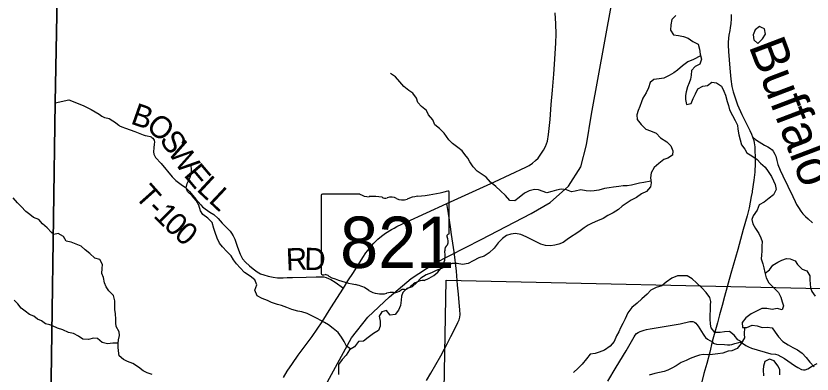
# Model space of a CAD drawing. Extents: x 0 to 34, y 0 to 22.
# Drawn here: x 26.994 to 29.042, y 17.376 to 18.296 of the extents above; entities that cross this region are included whole.
import ezdxf

# ---------------------------------------------------------------- set-up
doc = ezdxf.new("R2010")
doc.units = 0
for name, color, linetype in [('GM_X_Corporation', 7, 'Continuous'), ('GM_X_County_Road', 7, 'Continuous'), ('GM_X_Minor_Lake', 7, 'Continuous'), ('GM_X_Minor_River', 7, 'Continuous'), ('GM_X_Minor_River_Text', 7, 'Continuous'), ('GM_X_Rail_Line', 7, 'Continuous'), ('GM_X_State_Location', 7, 'Continuous'), ('GM_X_State_Route', 7, 'Continuous'), ('GM_X_State_Shield', 7, 'Continuous'), ('GM_X_Township_Road', 7, 'Continuous'), ('GM_X_Township_Road_Text', 7, 'Continuous')]:
    doc.layers.add(name, color=color, linetype=linetype)

msp = doc.modelspace()

# ---------------------------------------------------------------- linework, layer by layer
at = {"layer": 'GM_X_Corporation'}
for points in [[(26.6535, 14.621), (27.01, 14.6164), (27.046, 14.6155), (27.043, 14.755), (27.052, 15.403), (27.0676, 16.5549), (27.0694, 16.6556), (27.0775, 16.888), (27.0944, 18.0731), (27.1039, 18.5696), (27.1064, 18.6537), (27.3971, 18.6436), (28.3421, 18.6121), (28.7772, 18.6028), (29.0074, 18.5935), (29.6561, 18.5791), (29.6772, 18.5786), (30.101, 18.5701), (30.3167, 18.565), (30.3167, 20.9), (23.5167, 20.9)], [(26.3378, 16.673), (27.0694, 16.6556), (27.0775, 16.888), (27.0944, 18.0731), (27.1039, 18.5696), (27.1064, 18.6537), (27.3971, 18.6436), (28.3421, 18.6121), (28.7772, 18.6028), (29.0074, 18.5935), (29.6561, 18.5791), (29.6772, 18.5786), (30.101, 18.5701), (30.3167, 18.565), (30.3167, 20.9), (25.1014, 20.9)], [(23.5167, 14.1), (30.3167, 14.1), (30.3167, 18.565), (30.101, 18.5701), (29.6772, 18.5786), (29.6561, 18.5791), (29.0074, 18.5935), (28.7772, 18.6028), (28.3421, 18.6121), (27.3971, 18.6436), (27.1064, 18.6537), (27.1039, 18.5696), (27.0944, 18.0731), (27.0775, 16.888), (27.0694, 16.6556), (27.0676, 16.5549), (27.052, 15.403), (27.043, 14.755), (27.046, 14.6155), (27.01, 14.6164), (26.6535, 14.621)], [(27.1039, 18.5696), (27.0944, 18.0731), (27.0775, 16.888), (27.0694, 16.6556), (27.0676, 16.5549), (27.052, 15.403)]]:
    msp.add_lwpolyline(points, dxfattribs=at)
msp.add_lwpolyline([(28.101, 17.617), (29.1032, 17.5952), (29.0727, 16.6129), (28.0831, 16.631)], close=True, dxfattribs=at)
at = {"layer": 'GM_X_County_Road'}
for points in [[(28.8892, 17.985), (28.8967, 17.9784), (28.9067, 17.9721), (28.9203, 17.9642), (28.9286, 17.9593), (28.9357, 17.9549), (28.9395, 17.9518), (28.942, 17.9488), (28.9469, 17.9409), (28.9489, 17.9356), (28.9521, 17.9245), (28.9546, 17.914), (28.9602, 17.9), (28.9676, 17.8852), (28.9803, 17.8583), (28.9927, 17.8318), (28.9987, 17.8193), (29.0027, 17.8111), (29.0076, 17.8036), (29.0137, 17.7947), (29.0191, 17.7877), (29.0254, 17.7809), (29.032, 17.7744), (29.0439, 17.764)], [(28.05, 17.359), (28.0611, 17.3783), (28.0874, 17.423), (28.0968, 17.4403), (28.1038, 17.4534), (28.1133, 17.4724), (28.1213, 17.4887), (28.1312, 17.5081), (28.1345, 17.5154), (28.1361, 17.5224), (28.137, 17.5285), (28.1365, 17.5412), (28.1344, 17.5599), (28.1323, 17.5808), (28.1301, 17.6041), (28.1277, 17.6398), (28.1217, 17.69), (28.1147, 17.7345), (28.1118, 17.7543), (28.107, 17.7883), (28.1029, 17.8137)]]:
    msp.add_lwpolyline(points, dxfattribs=at)
at = {"layer": 'GM_X_Minor_Lake'}
for points in [[(28.9122, 18.2663), (28.9071, 18.2689), (28.8957, 18.2602), (28.8908, 18.2473), (28.8927, 18.2344), (28.9032, 18.2249)], [(28.9032, 18.2249), (28.9146, 18.237), (28.9222, 18.2491), (28.9199, 18.2624), (28.9122, 18.2663)]]:
    msp.add_lwpolyline(points, dxfattribs=at)
at = {"layer": 'GM_X_Minor_River'}
for points in [[(28.692, 18.2972), (28.6817, 18.287), (28.6787, 18.2733), (28.6783, 18.2597), (28.6858, 18.2476), (28.6987, 18.2453), (28.7112, 18.243), (28.7233, 18.2384), (28.7357, 18.2304), (28.7497, 18.2236), (28.7527, 18.2107), (28.7542, 18.1978), (28.7583, 18.1849), (28.7534, 18.1724), (28.7416, 18.1656), (28.7322, 18.1554), (28.7314, 18.1433), (28.7295, 18.1334), (28.7261, 18.1236), (28.7223, 18.1141), (28.7188, 18.1008), (28.7169, 18.0913), (28.7169, 18.0815), (28.7195, 18.0686), (28.7316, 18.0709), (28.7366, 18.0837), (28.7426, 18.0959), (28.7487, 18.1084), (28.7616, 18.1152), (28.7733, 18.117), (28.7843, 18.1254), (28.7968, 18.1238), (28.8092, 18.1155), (28.8153, 18.103), (28.8194, 18.0923), (28.8239, 18.0757), (28.8273, 18.0654), (28.8299, 18.0544), (28.8378, 18.0404), (28.8446, 18.0275), (28.8503, 18.015), (28.8514, 18.0047), (28.8536, 17.9903), (28.8574, 17.9774), (28.8608, 17.9649), (28.8694, 17.9536), (28.8743, 17.9441), (28.8875, 17.9361), (28.9015, 17.9274), (28.9094, 17.9179), (28.9219, 17.9072), (28.9298, 17.8959), (28.9377, 17.8837), (28.9434, 17.8723), (28.9475, 17.8625), (28.9498, 17.8496), (28.9429, 17.8367), (28.932, 17.828), (28.9191, 17.8178), (28.9062, 17.8102), (28.9013, 17.797), (28.8907, 17.7826), (28.8876, 17.7727), (28.8902, 17.7617), (28.897, 17.75), (28.9057, 17.7367), (28.911, 17.7261), (28.914, 17.7162), (28.9132, 17.7048), (28.9132, 17.692), (28.912, 17.6817), (28.9116, 17.6719)], [(28.7555, 18.1936), (28.7371, 18.1842), (28.7228, 18.1778), (28.7091, 18.1675), (28.6966, 18.1566), (28.6868, 18.1501), (28.6747, 18.143), (28.6614, 18.1361), (28.6489, 18.1339), (28.6357, 18.1324), (28.6259, 18.1248), (28.6217, 18.1112), (28.6152, 18.0987), (28.6072, 18.085), (28.6038, 18.0756), (28.5989, 18.0635), (28.5951, 18.0528), (28.5917, 18.0419), (28.5928, 18.0294), (28.6026, 18.0168), (28.615, 18.0054), (28.6267, 18.0009), (28.6411, 17.9944), (28.6528, 17.983), (28.6687, 17.9724), (28.6792, 17.9618), (28.6845, 17.9493), (28.683, 17.9383), (28.6709, 17.9307), (28.6606, 17.9269), (28.6485, 17.9167), (28.6364, 17.9069), (28.6281, 17.8928), (28.6269, 17.8796), (28.628, 17.8671), (28.6269, 17.8568), (28.6162, 17.8447), (28.6038, 17.8387), (28.5905, 17.8296), (28.5769, 17.8224), (28.567, 17.8156), (28.5542, 17.8069), (28.5443, 17.7982), (28.5303, 17.7903), (28.5167, 17.7831), (28.5049, 17.7759), (28.4902, 17.7691), (28.4762, 17.7634), (28.466, 17.7581), (28.4561, 17.7517), (28.4421, 17.7411), (28.416, 17.7237), (28.402, 17.7142), (28.391, 17.7097), (28.3804, 17.7071), (28.3698, 17.7056), (28.3569, 17.706), (28.3449, 17.7094), (28.3339, 17.7147), (28.3203, 17.7219), (28.3071, 17.7284), (28.2927, 17.7341), (28.2791, 17.7371), (28.2674, 17.7356), (28.256, 17.7319), (28.2458, 17.7239), (28.2344, 17.7129), (28.2242, 17.6997), (28.2117, 17.6876), (28.1985, 17.6789), (28.1852, 17.6747), (28.1705, 17.6664), (28.1576, 17.66), (28.1428, 17.6573), (28.1296, 17.6596), (28.1156, 17.6596), (28.1027, 17.6536), (28.0891, 17.6471), (28.0751, 17.6419), (28.063, 17.6362), (28.0498, 17.6305), (28.0361, 17.6222), (28.0251, 17.6108), (28.013, 17.5999), (27.9998, 17.5957), (27.9895, 17.5855), (27.9857, 17.576), (27.985, 17.5658), (27.9838, 17.5521), (27.9785, 17.54), (27.9694, 17.529), (27.9569, 17.5272), (27.9475, 17.5389), (27.935, 17.5359), (27.9289, 17.5245), (27.9308, 17.5116), (27.9315, 17.4988), (27.927, 17.4878), (27.9137, 17.4798), (27.9005, 17.4696), (27.8883, 17.4605)], [(28.6276, 17.8718), (28.6099, 17.8679), (28.5981, 17.866), (28.5879, 17.8633), (28.5777, 17.8611), (28.5664, 17.8596), (28.5561, 17.8592), (28.5456, 17.8581), (28.5319, 17.8558), (28.5202, 17.8539), (28.5081, 17.8524), (28.4934, 17.8487), (28.482, 17.8468), (28.4718, 17.8461), (28.4612, 17.8468), (28.4472, 17.8491), (28.4332, 17.8457), (28.423, 17.8442), (28.4102, 17.8488), (28.3969, 17.8511), (28.3848, 17.8484), (28.3727, 17.8447), (28.3599, 17.8416), (28.3383, 17.8489), (28.3281, 17.8496), (28.3145, 17.8463), (28.3024, 17.8402), (28.2887, 17.8292), (28.2774, 17.8209), (28.2649, 17.8221), (28.254, 17.8346), (28.2407, 17.8467), (28.2283, 17.8574), (28.2151, 17.8691), (28.2038, 17.8813), (28.1936, 17.8885), (28.1807, 17.8968), (28.1705, 17.9086), (28.1619, 17.9207), (28.1566, 17.9302), (28.1487, 17.9397), (28.1419, 17.9492), (28.1313, 17.9583), (28.1173, 17.9682), (28.1075, 17.9777), (28.0958, 17.9951), (28.0838, 18.0065), (28.0717, 18.0164), (28.0668, 18.0293), (28.0558, 18.0422), (28.0506, 18.0528), (28.0373, 18.063), (28.0283, 18.0733), (28.0242, 18.0843), (28.0151, 18.0972), (28.0049, 18.1044), (27.9917, 18.1143), (27.9815, 18.1268), (27.9702, 18.1393), (27.9577, 18.148)], [(27.8555, 17.4401), (27.8448, 17.4477), (27.8384, 17.4598), (27.8316, 17.4708), (27.8234, 17.4826), (27.8101, 17.4925), (27.7981, 17.5019), (27.7882, 17.508), (27.7784, 17.5133), (27.7686, 17.519), (27.7539, 17.5263), (27.7429, 17.5312), (27.7297, 17.5358), (27.7191, 17.5373), (27.7036, 17.5419), (27.6907, 17.5468), (27.6775, 17.5518), (27.6673, 17.5548), (27.6511, 17.5601), (27.6409, 17.5647), (27.6276, 17.5696), (27.6148, 17.5772), (27.6084, 17.5913), (27.6141, 17.6053), (27.6085, 17.6182), (27.5964, 17.6273), (27.5816, 17.6368), (27.5707, 17.6489), (27.5616, 17.6592), (27.5533, 17.6694), (27.5477, 17.6797), (27.5364, 17.691), (27.5254, 17.7028), (27.5179, 17.7123), (27.5119, 17.7248), (27.5062, 17.7392), (27.5028, 17.7502), (27.4987, 17.765), (27.4874, 17.776), (27.4745, 17.7859), (27.4685, 17.7954), (27.4647, 17.8098), (27.458, 17.8219), (27.4474, 17.8337), (27.4357, 17.8451), (27.4319, 17.8545), (27.4346, 17.8655), (27.4411, 17.8788), (27.4449, 17.8894), (27.4453, 17.9), (27.4449, 17.9133)], [(27.085, 17.7399), (27.0738, 17.7519), (27.0624, 17.7616), (27.0528, 17.7725), (27.0392, 17.7784), (27.0293, 17.7855), (27.0194, 17.7934), (27.0072, 17.8061), (26.998, 17.8159), (26.987, 17.8283)], [(27.344, 17.3748), (27.3312, 17.379), (27.3214, 17.3843), (27.3093, 17.3938), (27.2949, 17.4033), (27.2813, 17.4082), (27.2708, 17.4132), (27.2591, 17.4226), (27.2579, 17.4352), (27.2568, 17.4446), (27.2569, 17.4545), (27.2576, 17.464), (27.2599, 17.4746), (27.2592, 17.4844), (27.252, 17.4981), (27.2505, 17.5076), (27.2509, 17.517), (27.2498, 17.5303), (27.2479, 17.5417), (27.248, 17.5644), (27.2446, 17.5773), (27.2325, 17.5898), (27.2261, 17.6001), (27.222, 17.6099), (27.2194, 17.6236), (27.2145, 17.6338), (27.2156, 17.6471), (27.2168, 17.6573), (27.2096, 17.6702), (27.1971, 17.674), (27.1836, 17.6854), (27.1722, 17.6953), (27.162, 17.7044), (27.1488, 17.7094), (27.1356, 17.7147), (27.1227, 17.7174), (27.1159, 17.7295), (27.1027, 17.7367), (27.091, 17.7341), (27.085, 17.7399)], [(28.9116, 17.6719), (28.9154, 17.659), (28.9184, 17.6491), (28.921, 17.6366), (28.9244, 17.623), (28.9308, 17.6104), (28.9561, 17.585), (28.9617, 17.5733), (28.9659, 17.5615), (28.9692, 17.5513), (28.9658, 17.5406), (28.953, 17.5445), (28.9401, 17.5418), (28.9261, 17.5441), (28.9136, 17.5441), (28.8996, 17.5373), (28.886, 17.5309), (28.8724, 17.5207), (28.8625, 17.5082), (28.8636, 17.4953), (28.875, 17.4957), (28.8879, 17.5013), (28.9011, 17.4998), (28.9139, 17.4952), (28.9272, 17.4967), (28.94, 17.4944), (28.9476, 17.4838), (28.9559, 17.4717), (28.9672, 17.4599), (28.9808, 17.4508), (28.9929, 17.4443), (29.0046, 17.4383), (29.017, 17.4299), (29.0276, 17.4181), (29.037, 17.406), (29.048, 17.3946)], [(28.9214, 17.6348), (28.9331, 17.6438), (28.9418, 17.6555), (28.954, 17.6635), (28.9646, 17.6688), (28.9763, 17.6725), (28.9865, 17.6718), (28.9993, 17.6668), (29.005, 17.657), (29.0167, 17.6452), (29.0292, 17.641), (29.0363, 17.6285), (29.0371, 17.6175), (29.0374, 17.6073), (29.0385, 17.5978), (29.0419, 17.5883), (29.0506, 17.5762)], [(28.8622, 17.4579), (28.8515, 17.4635), (28.842, 17.476), (28.8303, 17.4851), (28.8175, 17.4844), (28.8058, 17.4825), (28.7925, 17.4825), (28.7831, 17.4943), (28.7808, 17.5038), (28.7805, 17.5174), (28.7805, 17.5276), (28.7809, 17.5401), (28.7813, 17.553), (28.7817, 17.5625), (28.7798, 17.5727), (28.77, 17.5853), (28.7591, 17.5978), (28.7455, 17.6103), (28.7338, 17.6202), (28.7213, 17.6278), (28.7077, 17.6282), (28.696, 17.6286), (28.6812, 17.6225), (28.6672, 17.6119), (28.6555, 17.6025), (28.6415, 17.5983), (28.6279, 17.5915), (28.618, 17.5809), (28.6047, 17.5688), (28.5922, 17.5582), (28.5786, 17.5469), (28.568, 17.5332), (28.5612, 17.5177), (28.5555, 17.5056), (28.5494, 17.4942), (28.5452, 17.484), (28.5391, 17.4737), (28.5331, 17.4594), (28.5225, 17.4476), (28.5084, 17.437), (28.4944, 17.4321), (28.4842, 17.4287), (28.4717, 17.4268), (28.4619, 17.4147), (28.4505, 17.4015), (28.4407, 17.3909), (28.4289, 17.3795)], [(27.0814, 17.5025), (27.0703, 17.5052), (27.06, 17.5127), (27.049, 17.5171), (27.0395, 17.5246), (27.0285, 17.529), (27.0175, 17.5373), (27.0072, 17.5451), (26.9984, 17.556), (26.9889, 17.5654)], [(27.2569, 17.4549), (27.2432, 17.4556), (27.2292, 17.4534), (27.2153, 17.4568), (27.2036, 17.4671), (27.1937, 17.4678), (27.1805, 17.4648), (27.1661, 17.4656), (27.1544, 17.4736), (27.1416, 17.4797), (27.1287, 17.4827), (27.1147, 17.4899), (27.1004, 17.4941), (27.0879, 17.4998), (27.0814, 17.5025)], [(28.8688, 17.4955), (28.8674, 17.4782), (28.8685, 17.4688), (28.8602, 17.4544), (28.8499, 17.4415), (28.8363, 17.4355), (28.8265, 17.4347), (28.8128, 17.4294), (28.8, 17.4279), (28.7864, 17.4257), (28.7724, 17.4253), (28.7625, 17.4257), (28.7527, 17.4242), (28.7421, 17.4212), (28.7292, 17.4159), (28.7186, 17.411), (28.7058, 17.4057), (28.6925, 17.3974), (28.6815, 17.3909), (28.6713, 17.386), (28.6615, 17.3826), (28.6377, 17.3773), (28.6233, 17.3728)], [(27.8883, 17.4605), (27.8755, 17.4594), (27.8653, 17.4461), (27.8524, 17.4382), (27.844, 17.4246), (27.8334, 17.4132), (27.8236, 17.4007), (27.8235, 17.3874), (27.8239, 17.3746)], [(28.9591, 17.3739), (28.9591, 17.3875), (28.9546, 17.397), (28.9452, 17.4099), (28.9327, 17.4137), (28.921, 17.408), (28.9171, 17.3959), (28.9167, 17.3864), (28.9175, 17.3717)]]:
    msp.add_lwpolyline(points, dxfattribs=at)
at = {"layer": 'GM_X_Rail_Line'}
msp.add_lwpolyline([(27.3982, 16.1548), (27.3854, 16.3634), (27.3867, 16.4413), (27.3961, 16.5113), (27.412, 16.582), (27.4321, 16.6447), (27.4659, 16.7237), (27.5061, 16.8023), (27.629, 17.0326), (27.7235, 17.2242), (27.8569, 17.4686), (27.899, 17.522), (27.9555, 17.5744), (28.0109, 17.6216), (28.0703, 17.6598), (28.1907, 17.7214), (28.3198, 17.7886), (28.3682, 17.817), (28.4153, 17.8583), (28.4471, 17.9079), (28.4621, 17.965), (28.4748, 18.0437), (28.5781, 18.607)], dxfattribs=at)
at = {"layer": 'GM_X_State_Route'}
for points in [[(27.6827, 17.3674), (27.6916, 17.3831), (27.7051, 17.4033), (27.7205, 17.4248), (27.7559, 17.4725), (27.782, 17.5104), (27.804, 17.5457), (27.8366, 17.5967), (27.8483, 17.6153), (27.8621, 17.6368), (27.8867, 17.6756), (27.8946, 17.6872), (27.8983, 17.6925), (27.9024, 17.6979), (27.9088, 17.7056), (27.915, 17.7124), (27.9208, 17.7182), (27.9255, 17.7226), (27.9305, 17.7269), (27.9376, 17.7325), (27.9446, 17.7377), (27.9603, 17.7472), (27.9674, 17.751), (27.9741, 17.7546), (27.9978, 17.7659), (28.1029, 17.8137), (28.2256, 17.8698), (28.3063, 17.9071), (28.3145, 17.9116), (28.323, 17.9179), (28.331, 17.9244), (28.3375, 17.9309), (28.343, 17.9382), (28.3515, 17.9511), (28.3565, 17.9605), (28.3616, 17.9743), (28.3643, 17.991), (28.3682, 18.0299), (28.3711, 18.0683), (28.3742, 18.1055), (28.3776, 18.1467), (28.3804, 18.1847), (28.3832, 18.227), (28.3836, 18.2491), (28.3829, 18.2756), (28.3815, 18.3037)], [(28.8341, 18.3), (28.8341, 18.2888), (28.8338, 18.2764), (28.8321, 18.2649), (28.8305, 18.2584), (28.8281, 18.2465), (28.8272, 18.2391), (28.8262, 18.2273), (28.8264, 18.2206), (28.8275, 18.2046), (28.8307, 18.1614), (28.8333, 18.1335), (28.8363, 18.1146), (28.8393, 18.1013), (28.8425, 18.0907), (28.8505, 18.0677), (28.8618, 18.0431), (28.8713, 18.0238), (28.8822, 18.0015), (28.8864, 17.9918), (28.8892, 17.985), (28.8924, 17.976), (28.8937, 17.9702), (28.8949, 17.96), (28.8956, 17.947), (28.896, 17.9367), (28.8959, 17.9174), (28.8951, 17.8944), (28.893, 17.8738), (28.8885, 17.8455), (28.8881, 17.8434)], [(28.8881, 17.8434), (28.8858, 17.8322), (28.8803, 17.8032), (28.8752, 17.7823), (28.8655, 17.7469), (28.8513, 17.6958), (28.8336, 17.6342), (28.8171, 17.5747), (28.811, 17.552), (28.8042, 17.5281), (28.799, 17.5074), (28.7858, 17.4592), (28.779, 17.432), (28.7714, 17.4032), (28.7643, 17.3775), (28.756, 17.3452)]]:
    msp.add_lwpolyline(points, dxfattribs=at)
at = {"layer": 'GM_X_State_Shield'}
for p, q in [((27.7794, 17.8345), (27.7794, 17.6343)), ((27.8791, 17.8379), (27.7826, 17.8379)), ((28.109, 17.7382), (28.109, 17.8429)), ((28.1089, 17.7382), (28.109, 17.7382))]:
    msp.add_line(p, q, dxfattribs=at)
for centre, major_axis, start_param, end_param in [((27.9916, 18.1107), (0.3495, 0), 4.814394, 5.042369), ((28.1053, 17.8433), (0.00367, 0), 6.141152, 7.989035), ((27.7832, 17.8349), (0.00382, 0), 1.712693, 3.28349), ((27.9021, 17.8611), (0.037, 0), 4.042523, 4.731795), ((27.9144, 17.7256), (0.133, 0), 1.404758, 1.657858), ((27.9446, 17.8359), (0.0107, 0), 3.836095, 5.185415), ((27.9603, 17.8128), (0.0222, 0), 0.950623, 2.079405), ((27.989, 17.8445), (0.0267, 0), 4.081561, 5.145723), ((28.0361, 17.7768), (0.0703, 0), 1.699011, 2.107814), ((28.1081, 17.7305), (0.00568, 0), 1.883978, 3.671073), ((28.072, 17.7173), (0.0341, 0), 5.934695, 6.695948), ((28.1051, 17.7378), (0.00393, 0), 5.05454, 6.418171), ((28.1221, 17.6944), (0.0248, 0), 2.387724, 3.262537), ((28.0111, 17.6811), (0.0874, 0), 5.101752, 6.440018), ((27.7832, 17.6339), (0.00385, 0), 3.00124, 4.508301), ((27.7838, 17.6544), (0.0294, 0), 4.665946, 4.897461), ((27.7898, 17.6228), (0.0106, 0), 0.519207, 1.627899), ((27.9236, 17.8026), (0.2524, 0), 4.195997, 4.488961), ((27.8484, 17.5444), (0.079, 0), 0.823519, 1.323587), ((27.9873, 17.615), (0.0282, 0), 4.937069, 5.64225), ((28.048, 17.5782), (0.0479, 0), 1.647645, 2.488434), ((27.9338, 17.6218), (0.0501, 0), 4.026481, 4.996735), ((27.9627, 17.5526), (0.0412, 0), 1.495662, 1.94098), ((27.9664, 17.6068), (0.0267, 0), 4.691044, 5.507374), ((27.9905, 17.5874), (0.00752, 0), 1.147584, 2.315152)]:
    msp.add_ellipse(centre, major_axis=major_axis, ratio=0.8, start_param=start_param, end_param=end_param, dxfattribs=at)
at = {"layer": 'GM_X_Township_Road'}
for points in [[(27.0946, 18.0726), (27.1303, 18.0802), (27.1672, 18.0655), (27.187, 18.0558), (27.2082, 18.0436), (27.2117, 18.0409), (27.2148, 18.0383), (27.2181, 18.0365), (27.2219, 18.0351), (27.2258, 18.0341), (27.2299, 18.0335), (27.2334, 18.0325), (27.2436, 18.0266), (27.2497, 18.0222), (27.2552, 18.0176), (27.2585, 18.0149)], [(27.2585, 18.0149), (27.2601, 18.0136), (27.2662, 18.0106), (27.2755, 18.0073), (27.2997, 17.999), (27.3213, 17.9905), (27.3267, 17.9891), (27.3319, 17.9878), (27.3389, 17.9859), (27.3415, 17.9851), (27.3438, 17.9838), (27.3464, 17.982), (27.3481, 17.9796), (27.3493, 17.9764), (27.3501, 17.9712), (27.3494, 17.9663), (27.3484, 17.9574), (27.3477, 17.9464), (27.3486, 17.9405), (27.3503, 17.937), (27.3532, 17.9322), (27.3672, 17.9165), (27.3957, 17.8826), (27.4057, 17.873), (27.4155, 17.8653), (27.4225, 17.8606), (27.4292, 17.8564), (27.4348, 17.8511), (27.4403, 17.8448), (27.4565, 17.8249), (27.4693, 17.8103), (27.4735, 17.8055), (27.4806, 17.7999), (27.4864, 17.7957), (27.4929, 17.7916), (27.5028, 17.7855), (27.5139, 17.7752), (27.5192, 17.7694), (27.5247, 17.7632), (27.5325, 17.7559), (27.5401, 17.748), (27.5447, 17.7427), (27.5482, 17.7375), (27.5528, 17.7309), (27.5572, 17.7225), (27.564, 17.7015), (27.5708, 17.6839), (27.5768, 17.672), (27.5848, 17.663), (27.5949, 17.6541), (27.6045, 17.646), (27.615, 17.6385), (27.6231, 17.6335), (27.632, 17.6304), (27.643, 17.6274), (27.6558, 17.6245), (27.6669, 17.6232), (27.6811, 17.6229), (27.6921, 17.6235), (27.7058, 17.6241), (27.7405, 17.625), (27.7667, 17.6257), (27.7759, 17.6258), (27.7858, 17.6254), (27.7921, 17.624), (27.804, 17.6187), (27.8153, 17.612), (27.8366, 17.5967)], [(28.517, 17.3578), (28.5387, 17.3935), (28.564, 17.4359), (28.5847, 17.4718), (28.5872, 17.4757), (28.5903, 17.4798), (28.5947, 17.4829), (28.6003, 17.4854), (28.605, 17.4872), (28.61, 17.4886), (28.6168, 17.4903), (28.6256, 17.4919), (28.6721, 17.4998), (28.7027, 17.5053), (28.7275, 17.5106), (28.7358, 17.5107), (28.7399, 17.5092), (28.7434, 17.5068), (28.7462, 17.5035), (28.7495, 17.4987), (28.762, 17.478), (28.7653, 17.4731), (28.768, 17.4696), (28.7734, 17.4657), (28.7796, 17.4618), (28.7858, 17.4592)], [(28.7858, 17.4592), (28.788, 17.4555), (28.7903, 17.454), (28.7963, 17.4525), (28.8167, 17.452), (28.8249, 17.4512), (28.8312, 17.4511), (28.8359, 17.4518), (28.8441, 17.4541), (28.854, 17.4572), (28.857, 17.4577), (28.8595, 17.4573), (28.8633, 17.4552), (28.8717, 17.4494), (28.8753, 17.4474), (28.879, 17.4456), (28.8869, 17.4425), (28.9364, 17.4282), (28.9483, 17.4266), (28.9543, 17.425), (28.9715, 17.4155), (28.9974, 17.3982), (29.0062, 17.3927), (29.0151, 17.3878), (29.0201, 17.3866), (29.0249, 17.3871), (29.0316, 17.3896), (29.0411, 17.3953), (29.0559, 17.4032)]]:
    msp.add_lwpolyline(points, dxfattribs=at)

# ---------------------------------------------------------------- texts
at = {"layer": 'GM_X_Minor_River_Text'}
msp.add_text('Buffalo', height=0.09468, rotation=290.7843, dxfattribs=at).set_placement((28.8786, 18.2188))
at = {"layer": 'GM_X_State_Location'}
for s in ['s', 'r']:
    msp.add_text(s, height=0.000189, dxfattribs=at).set_placement((27.9405, 17.7211))
msp.add_text('821', height=0.000189, rotation=0, dxfattribs=at).set_placement((27.8736, 17.7073))
at = {"layer": 'GM_X_State_Shield'}
msp.add_text('821', height=0.13184, dxfattribs=at).set_placement((27.8279, 17.6485))
at = {"layer": 'GM_X_Township_Road_Text'}
for s, rotation, p in [('B', 340.6591, (27.2866, 18.0199)), ('O', 320.2103, (27.326, 18.0071)), ('S', 303.839, (27.3616, 17.9782)), ('W', 303.9521, (27.383, 17.9463)), ('E', 310.1964, (27.4238, 17.8863)), ('L', 317.127, (27.4565, 17.8484)), ('T', 311.7435, (27.2977, 17.8316)), ('L', 316.7397, (27.4875, 17.8196)), ('-', 315.4195, (27.3287, 17.797)), ('1', 315.6517, (27.3455, 17.7805)), ('0', 316.6176, (27.3713, 17.7553)), ('0', 318.6466, (27.3984, 17.7297)), ('R', 2.4792, (27.6897, 17.6418)), ('D', 358.5464, (27.7353, 17.6438))]:
    msp.add_text(s, height=0.0568, rotation=rotation, dxfattribs=at).set_placement(p)

doc.saveas('drawing.dxf')
